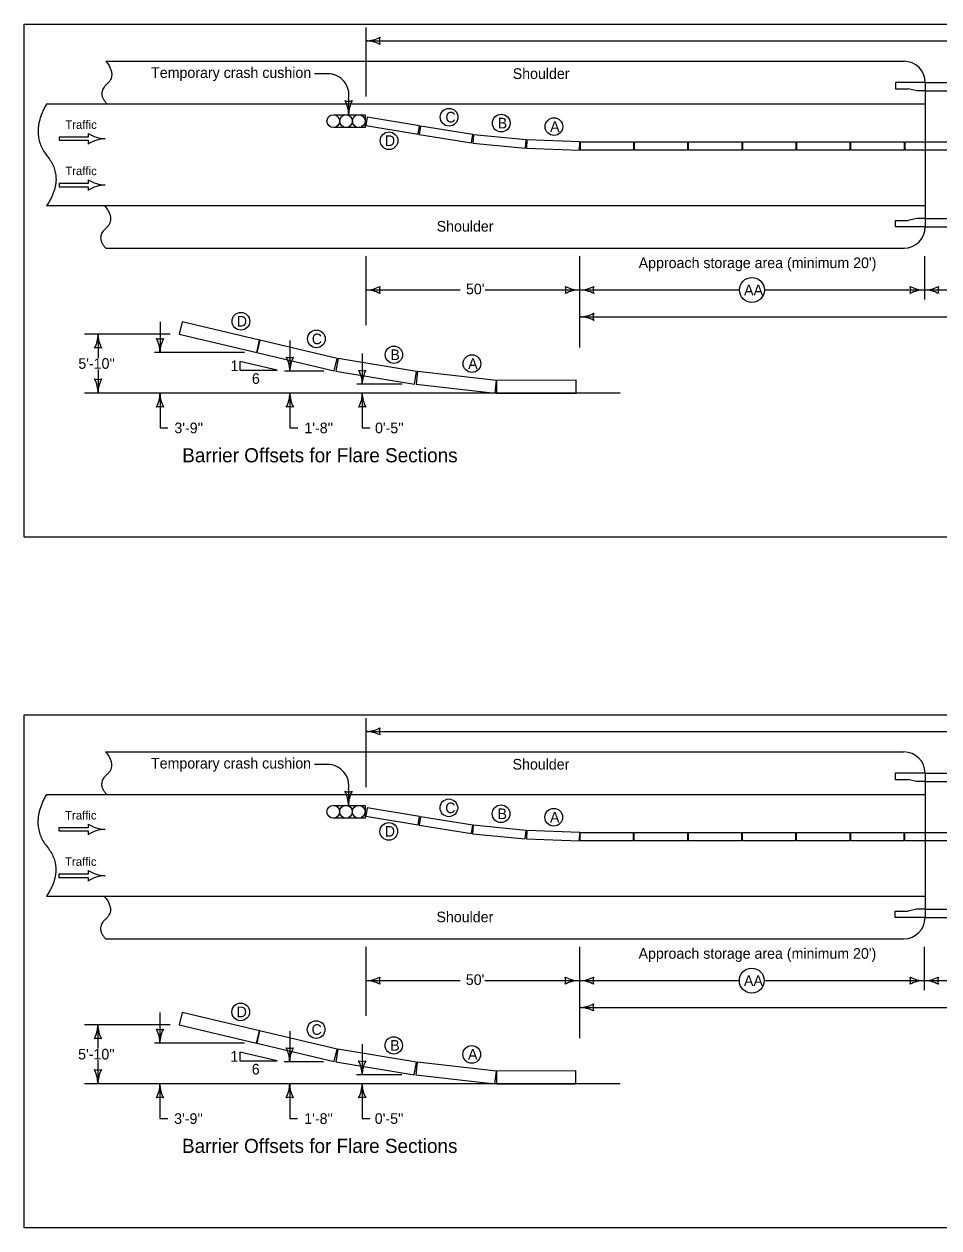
# Model space of a CAD drawing. Extents: x 10148 to 16528, y 8070 to 10905.
# Drawn here: x 10148 to 11441, y 9204 to 10905 of the extents above; entities that cross this region are included whole.
import ezdxf

# ---------------------------------------------------------------- set-up
doc = ezdxf.new("R2010")
doc.units = 0
for name, color, linetype in [('Sheet_Table Border', 7, 'Continuous'), ('SheetText', 7, 'Continuous'), ('TC_Barrier', 7, 'Continuous'), ('TC_Bridge', 7, 'Continuous'), ('TC_PCCPavement', 7, 'Continuous'), ('TC_ShoulderGranular', 7, 'Continuous')]:
    doc.layers.add(name, color=color, linetype=linetype)

msp = doc.modelspace()

# ---------------------------------------------------------------- linework, layer by layer
at = {"layer": 'Sheet_Table Border'}
for p, q in [((10148, 10904.5), (13253, 10904.5)), ((10148, 10179.5), (10148, 10904.5)), ((13253, 10179.5), (10148, 10179.5)), ((10147.7, 9928.8), (13252.7, 9928.8)), ((10147.7, 9203.8), (10147.7, 9928.8)), ((13252.7, 9203.8), (10147.7, 9203.8))]:
    msp.add_line(p, q, dxfattribs=at)
at = {"layer": 'SheetText'}
for p, q in [((10148, 10904.5), (10148, 10904.5)), ((10630.9, 10899.6), (10630.9, 10802.1)), ((10630.9, 10880.9), (11509.4, 10880.9)), ((10577.1, 10834.3), (10558.4, 10834.3)), ((10606.6, 10798.9), (10606.6, 10776.4)), ((10238.5, 10750), (10238.5, 10744.8)), ((10238.5, 10744.8), (10197.3, 10744.8)), ((10197.3, 10744.8), (10197.3, 10740.3)), ((10197.3, 10740.3), (10238.5, 10740.3)), ((10238.5, 10740.3), (10238.5, 10735)), ((10262.4, 10742.5), (10262.4, 10742.5)), ((10238.5, 10684.6), (10238.5, 10679.3)), ((10238.5, 10679.3), (10197.3, 10679.3)), ((10197.3, 10679.3), (10197.3, 10674.8)), ((10197.3, 10674.8), (10238.5, 10674.8)), ((10238.5, 10674.8), (10238.5, 10669.6)), ((10262.4, 10677.1), (10262.4, 10677.1)), ((10630.9, 10576.7), (10630.9, 10479.2)), ((10933.1, 10576.7), (10933.1, 10447.6)), ((11420.6, 10576.7), (11420.6, 10515.5)), ((10630.9, 10528.9), (10764.3, 10528.9)), ((10799.6, 10528.9), (10933.1, 10528.9)), ((10933.1, 10528.9), (11159.2, 10528.9)), ((11194.5, 10528.9), (11420.6, 10528.9)), ((11420.6, 10528.9), (11563.8, 10528.9)), ((10340, 10484), (10340, 10440.5)), ((10933.1, 10491), (11523.9, 10491)), ((10354.5, 10466.5), (10233.4, 10466.5)), ((10252.4, 10466.5), (10252.4, 10433)), ((10523.5, 10457.6), (10523.5, 10414.1)), ((10459.5, 10440.5), (10332.2, 10440.5)), ((10505.6, 10415.6), (10453, 10428)), ((10453, 10428), (10453, 10415.6)), ((10625.9, 10439), (10625.9, 10395.6)), ((10252.4, 10416.7), (10252.4, 10383.2)), ((10453, 10415.6), (10505.6, 10415.6)), ((10571.4, 10414.1), (10515.8, 10414.1)), ((10682.2, 10395.6), (10618.2, 10395.6)), ((10990.7, 10383.2), (10233.4, 10383.2)), ((10340, 10383.2), (10340, 10334)), ((10523.5, 10383.2), (10523.5, 10334)), ((10625.9, 10383.2), (10625.9, 10356.3)), ((10625.9, 10356.3), (10625.9, 10334)), ((10340, 10334), (10351.1, 10334)), ((10523.5, 10334), (10534.7, 10334)), ((10625.9, 10334), (10637.1, 10334)), ((10147.7, 9928.8), (10147.7, 9928.8)), ((10630.7, 9923.9), (10630.7, 9826.4)), ((10630.7, 9905.2), (11509.2, 9905.2)), ((10576.9, 9858.6), (10558.2, 9858.6)), ((10606.4, 9823.2), (10606.4, 9800.7)), ((10238.3, 9769.1), (10197, 9769.1)), ((10197, 9769.1), (10197, 9764.6)), ((10197, 9764.6), (10238.3, 9764.6)), ((10238.3, 9774.3), (10238.3, 9769.1)), ((10238.3, 9764.6), (10238.3, 9759.3)), ((10262.2, 9766.8), (10262.2, 9766.8)), ((10238.3, 9703.6), (10197, 9703.6)), ((10197, 9703.6), (10197, 9699.1)), ((10197, 9699.1), (10238.3, 9699.1)), ((10238.3, 9708.9), (10238.3, 9703.6)), ((10238.3, 9699.1), (10238.3, 9693.9)), ((10262.2, 9701.4), (10262.2, 9701.4)), ((10630.7, 9601), (10630.7, 9503.5)), ((10932.8, 9601), (10932.8, 9471.9)), ((11420.3, 9601), (11420.3, 9539.8)), ((10630.7, 9553.2), (10764.1, 9553.2)), ((10799.4, 9553.2), (10932.8, 9553.2)), ((10932.8, 9553.2), (11158.9, 9553.2)), ((11194.2, 9553.2), (11420.3, 9553.2)), ((11420.3, 9553.2), (11563.5, 9553.2)), ((10339.8, 9508.3), (10339.8, 9464.8)), ((10932.8, 9515.3), (11523.6, 9515.3)), ((10354.3, 9490.8), (10233.1, 9490.8)), ((10252.1, 9490.8), (10252.1, 9457.3)), ((10523.3, 9481.9), (10523.3, 9438.4)), ((10459.2, 9464.8), (10332, 9464.8)), ((10625.7, 9463.3), (10625.7, 9419.9)), ((10252.1, 9441), (10252.1, 9407.5)), ((10505.4, 9439.9), (10452.7, 9452.3)), ((10452.7, 9452.3), (10452.7, 9439.9)), ((10452.7, 9439.9), (10505.4, 9439.9)), ((10571.1, 9438.4), (10515.6, 9438.4)), ((10990.5, 9407.5), (10233.1, 9407.5)), ((10339.8, 9407.5), (10339.8, 9358.3)), ((10523.3, 9407.5), (10523.3, 9358.3)), ((10682, 9419.9), (10617.9, 9419.9)), ((10625.7, 9407.5), (10625.7, 9380.6)), ((10625.7, 9380.6), (10625.7, 9358.3)), ((10339.8, 9358.3), (10350.9, 9358.3)), ((10523.3, 9358.3), (10534.5, 9358.3)), ((10625.7, 9358.3), (10636.8, 9358.3))]:
    msp.add_line(p, q, dxfattribs=at)
for centre, radius in [((10748.6, 10773), 12.5), ((10822.3, 10764.6), 12.5), ((10896.9, 10759.7), 12.5), ((10663.7, 10739.8), 12.5), ((11176.8, 10528.9), 17.6), ((10454.3, 10484.7), 12.5), ((10561, 10459.8), 12.5), ((10670.6, 10437.4), 12.2), ((10781, 10424.8), 12.5), ((10748.3, 9797.3), 12.5), ((10822.1, 9788.9), 12.5), ((10896.6, 9784), 12.5), ((10663.4, 9764.1), 12.5), ((11176.6, 9553.2), 17.6), ((10454, 9509), 12.5), ((10560.7, 9484.1), 12.5), ((10670.4, 9461.7), 12.2), ((10780.7, 9449), 12.5)]:
    msp.add_circle(centre, radius, dxfattribs=at)
for centre, radius, start, end in [((10630.9, 10923.4), 42.5, 270, 298.0725), ((10666.5, 10880.9), 16.4, 162.2666, 197.7334), ((10630.9, 10838.4), 42.5, 61.9275, 90), ((10577.1, 10804.3), 30, 349.6463, 90), ((10606.6, 10812), 16.4, 252.2666, 287.7333), ((10564.1, 10776.4), 42.5, 360, 28.0725), ((10649.1, 10776.4), 42.5, 151.9275, 180), ((10264.4, 10790.9), 48.4, 237.618, 267.648), ((10264.4, 10694.2), 48.4, 92.352, 122.382), ((10264.4, 10725.4), 48.4, 237.618, 267.648), ((10264.4, 10628.8), 48.4, 92.352, 122.382), ((10630.9, 10571.4), 42.5, 270, 298.0725), ((10630.9, 10486.4), 42.5, 61.9275, 90), ((10666.5, 10528.9), 16.4, 162.2666, 197.7334), ((10897.4, 10528.9), 16.4, 342.2666, 17.7333), ((10933.1, 10571.4), 42.5, 241.9275, 270), ((10933.1, 10486.4), 42.5, 90, 118.0725), ((10933.1, 10571.4), 42.5, 270, 298.0725), ((10933.1, 10486.4), 42.5, 61.9275, 90), ((10968.7, 10528.9), 16.4, 162.2666, 197.7334), ((11384.9, 10528.9), 16.4, 342.2666, 17.7333), ((11420.6, 10571.4), 42.5, 241.9275, 270), ((11420.6, 10486.4), 42.5, 90, 118.0725), ((11420.6, 10571.4), 42.5, 270, 298.0725), ((11420.6, 10486.4), 42.5, 61.9275, 90), ((11456.2, 10528.9), 16.4, 162.2666, 197.7334), ((10933.1, 10533.5), 42.5, 270, 298.0725), ((10968.7, 10491), 16.4, 162.2666, 197.7334), ((10933.1, 10448.5), 42.5, 61.9275, 90), ((10209.9, 10466.5), 42.5, 331.9275, 0), ((10294.9, 10466.5), 42.5, 180, 208.0725), ((10340, 10476.2), 16.4, 252.2666, 287.7334), ((10297.5, 10440.5), 42.5, 0, 28.0725), ((10382.5, 10440.5), 42.5, 151.9275, 180), ((10252.4, 10430.9), 16.4, 72.2666, 107.7334), ((10523.5, 10449.8), 16.4, 252.2666, 287.7334), ((10481, 10414.1), 42.5, 0, 28.0725), ((10566, 10414.1), 42.5, 151.9275, 180), ((10625.9, 10431.2), 16.4, 252.2666, 287.7334), ((10583.4, 10395.6), 42.5, 0, 28.0725), ((10668.4, 10395.6), 42.5, 151.9275, 180), ((10252.4, 10418.9), 16.4, 252.2666, 287.7334), ((10209.9, 10383.2), 42.5, 0, 28.0725), ((10294.9, 10383.2), 42.5, 151.9275, 180), ((10297.5, 10383.2), 42.5, 331.9275, 0), ((10382.5, 10383.2), 42.5, 180, 208.0725), ((10481, 10383.2), 42.5, 331.9275, 0), ((10566, 10383.2), 42.5, 180, 208.0725), ((10583.4, 10383.2), 42.5, 331.9275, 0), ((10668.4, 10383.2), 42.5, 180, 208.0725), ((10340, 10347.6), 16.4, 72.2666, 107.7334), ((10523.5, 10347.6), 16.4, 72.2666, 107.7334), ((10625.9, 10347.6), 16.4, 72.2666, 107.7334), ((10630.7, 9947.7), 42.5, 270, 298.0725), ((10630.7, 9862.7), 42.5, 61.9275, 90), ((10666.3, 9905.2), 16.4, 162.2666, 197.7334), ((10576.9, 9828.6), 30, 349.6463, 90), ((10606.4, 9836.3), 16.4, 252.2666, 287.7333), ((10563.9, 9800.7), 42.5, 360, 28.0725), ((10648.9, 9800.7), 42.5, 151.9275, 180), ((10264.2, 9815.2), 48.4, 237.618, 267.648), ((10264.2, 9718.5), 48.4, 92.352, 122.382), ((10264.2, 9749.7), 48.4, 237.618, 267.648), ((10264.2, 9653.1), 48.4, 92.352, 122.382), ((10630.7, 9595.7), 42.5, 270, 298.0725), ((10666.3, 9553.2), 16.4, 162.2666, 197.7334), ((10897.2, 9553.2), 16.4, 342.2666, 17.7333), ((10932.8, 9595.7), 42.5, 241.9275, 270), ((10932.8, 9595.7), 42.5, 270, 298.0725), ((10968.5, 9553.2), 16.4, 162.2666, 197.7334), ((11384.7, 9553.2), 16.4, 342.2666, 17.7333), ((11420.3, 9595.7), 42.5, 241.9275, 270), ((11420.3, 9595.7), 42.5, 270, 298.0725), ((11456, 9553.2), 16.4, 162.2666, 197.7334), ((10630.7, 9510.7), 42.5, 61.9275, 90), ((10932.8, 9510.7), 42.5, 90, 118.0725), ((10932.8, 9510.7), 42.5, 61.9275, 90), ((11420.3, 9510.7), 42.5, 90, 118.0725), ((11420.3, 9510.7), 42.5, 61.9275, 90), ((10932.8, 9557.8), 42.5, 270, 298.0725), ((10932.8, 9472.8), 42.5, 61.9275, 90), ((10968.5, 9515.3), 16.4, 162.2666, 197.7334), ((10209.6, 9490.8), 42.5, 331.9275, 0), ((10294.6, 9490.8), 42.5, 180, 208.0725), ((10339.8, 9500.5), 16.4, 252.2666, 287.7334), ((10297.3, 9464.8), 42.5, 0, 28.0725), ((10382.3, 9464.8), 42.5, 151.9275, 180), ((10252.1, 9455.2), 16.4, 72.2666, 107.7334), ((10523.3, 9474.1), 16.4, 252.2666, 287.7334), ((10480.8, 9438.4), 42.5, 0, 28.0725), ((10565.8, 9438.4), 42.5, 151.9275, 180), ((10625.7, 9455.5), 16.4, 252.2666, 287.7334), ((10583.2, 9419.9), 42.5, 0, 28.0725), ((10668.2, 9419.9), 42.5, 151.9275, 180), ((10252.1, 9443.2), 16.4, 252.2666, 287.7334), ((10209.6, 9407.5), 42.5, 0, 28.0725), ((10294.6, 9407.5), 42.5, 151.9275, 180), ((10297.3, 9407.5), 42.5, 331.9275, 0), ((10382.3, 9407.5), 42.5, 180, 208.0725), ((10480.8, 9407.5), 42.5, 331.9275, 0), ((10565.8, 9407.5), 42.5, 180, 208.0725), ((10583.2, 9407.5), 42.5, 331.9275, 0), ((10668.2, 9407.5), 42.5, 180, 208.0725), ((10339.8, 9371.9), 16.4, 72.2666, 107.7334), ((10523.3, 9371.9), 16.4, 72.2666, 107.7334), ((10625.7, 9371.9), 16.4, 72.2666, 107.7334)]:
    msp.add_arc(centre, radius, start, end, dxfattribs=at)
at = {"layer": 'TC_Barrier'}
for p, q in [((10585, 10776.4), (10630, 10776.4)), ((10630, 10776.4), (10630, 10758.4)), ((10630, 10758.4), (10585, 10758.4)), ((10628.8, 10764.1), (10630.1, 10763.8)), ((10630.6, 10760.4), (10630.6, 10760.4)), ((10584.8, 9800.7), (10629.8, 9800.7)), ((10629.8, 9800.7), (10629.8, 9782.7)), ((10629.8, 9782.7), (10584.8, 9782.7)), ((10628.6, 9788.4), (10629.9, 9788.1)), ((10630.3, 9784.7), (10630.3, 9784.7))]:
    msp.add_line(p, q, dxfattribs=at)
for points in [[(10706.9, 10760.8), (10632.8, 10772.9), (10630.9, 10761.1), (10704.9, 10748.9)], [(10782.3, 10748.4), (10708.3, 10760.5), (10706.4, 10748.7), (10780.4, 10736.6)], [(10857.8, 10741.2), (10783.1, 10748.3), (10782, 10736.3), (10856.6, 10729.2)], [(10933.5, 10738.2), (10858.6, 10741.2), (10858.1, 10729.2), (10933.1, 10726.2)], [(10934.3, 10738.2), (11009.3, 10738.2), (11009.3, 10726.2), (10934.3, 10726.2)], [(11010.8, 10738.2), (11085.8, 10738.2), (11085.8, 10726.2), (11010.8, 10726.2)], [(11087.3, 10738.2), (11162.3, 10738.2), (11162.3, 10726.2), (11087.3, 10726.2)], [(11163.8, 10738.2), (11238.8, 10738.2), (11238.8, 10726.2), (11163.8, 10726.2)], [(11240.3, 10738.2), (11315.3, 10738.2), (11315.3, 10726.2), (11240.3, 10726.2)], [(11316.8, 10738.2), (11391.8, 10738.2), (11391.8, 10726.2), (11316.8, 10726.2)], [(11393.3, 10738.2), (11468.3, 10738.2), (11468.3, 10726.2), (11393.3, 10726.2)], [(10480.8, 10458.1), (10371.3, 10484), (10367.2, 10466.5), (10476.6, 10440.6)], [(10590.6, 10432.2), (10481.1, 10458.1), (10476.9, 10440.5), (10586.4, 10414.6)], [(10702.6, 10413.5), (10591.7, 10431.9), (10588.7, 10414.1), (10699.7, 10395.7)], [(10815.7, 10401.1), (10703.9, 10413.5), (10701.9, 10395.6), (10813.8, 10383.2)], [(10928.2, 10401.3), (10815.7, 10401.2), (10815.7, 10383.2), (10928.2, 10383.3)], [(10706.6, 9785.1), (10632.6, 9797.2), (10630.7, 9785.4), (10704.7, 9773.2)], [(10782.1, 9772.7), (10708.1, 9784.8), (10706.2, 9773), (10780.2, 9760.9)], [(10857.5, 9765.5), (10782.9, 9772.6), (10781.7, 9760.6), (10856.4, 9753.5)], [(10933.3, 9762.5), (10858.4, 9765.5), (10857.9, 9753.5), (10932.8, 9750.5)], [(10934, 9762.5), (11009, 9762.5), (11009, 9750.5), (10934, 9750.5)], [(11010.5, 9762.5), (11085.5, 9762.5), (11085.5, 9750.5), (11010.5, 9750.5)], [(11087, 9762.5), (11162, 9762.5), (11162, 9750.5), (11087, 9750.5)], [(11163.5, 9762.5), (11238.5, 9762.5), (11238.5, 9750.5), (11163.5, 9750.5)], [(11240, 9762.5), (11315, 9762.5), (11315, 9750.5), (11240, 9750.5)], [(11316.5, 9762.5), (11391.5, 9762.5), (11391.5, 9750.5), (11316.5, 9750.5)], [(11393, 9762.5), (11468, 9762.5), (11468, 9750.5), (11393, 9750.5)], [(10480.6, 9482.4), (10371.1, 9508.3), (10366.9, 9490.8), (10476.4, 9464.9)], [(10590.3, 9456.5), (10480.8, 9482.4), (10476.7, 9464.8), (10586.2, 9438.9)], [(10702.4, 9437.8), (10591.4, 9456.2), (10588.5, 9438.4), (10699.5, 9420)], [(10815.5, 9425.4), (10703.7, 9437.8), (10701.7, 9419.9), (10813.5, 9407.5)], [(10928, 9425.6), (10815.5, 9425.5), (10815.5, 9407.5), (10928, 9407.6)]]:
    msp.add_lwpolyline(points, close=True, dxfattribs=at)
for centre in [(10585, 10767.4), (10585, 10767.4), (10603, 10767.4), (10603, 10767.4), (10621, 10767.4), (10621, 10767.4), (10584.8, 9791.7), (10584.8, 9791.7), (10602.8, 9791.7), (10602.8, 9791.7), (10620.8, 9791.7), (10620.8, 9791.7)]:
    msp.add_circle(centre, 9, dxfattribs=at)
at = {"layer": 'TC_Bridge'}
for p, q in [((11421.8, 10822), (11379.8, 10822)), ((11379.8, 10822), (11379.8, 10813)), ((11421.8, 10822), (11421.8, 10618)), ((11421.8, 10822), (11567.8, 10822)), ((11379.8, 10813), (11397.8, 10813)), ((11409.8, 10810), (11397.8, 10813)), ((11421.8, 10810), (11409.8, 10810)), ((11421.8, 10810), (11567.8, 10810)), ((11409.8, 10630), (11397.8, 10627)), ((11421.8, 10630), (11409.8, 10630)), ((11421.8, 10630), (11567.8, 10630)), ((11379.8, 10627), (11397.8, 10627)), ((11379.8, 10618), (11379.8, 10627)), ((11421.8, 10618), (11379.8, 10618)), ((11421.8, 10618), (11567.8, 10618)), ((11421.5, 9846.3), (11379.5, 9846.3)), ((11379.5, 9846.3), (11379.5, 9837.3)), ((11379.5, 9837.3), (11397.5, 9837.3)), ((11409.5, 9834.3), (11397.5, 9837.3)), ((11421.5, 9834.3), (11409.5, 9834.3)), ((11421.5, 9846.3), (11421.5, 9642.3)), ((11421.5, 9846.3), (11567.5, 9846.3)), ((11421.5, 9834.3), (11567.5, 9834.3)), ((11379.5, 9651.3), (11397.5, 9651.3)), ((11379.5, 9642.3), (11379.5, 9651.3)), ((11409.5, 9654.3), (11397.5, 9651.3)), ((11421.5, 9654.3), (11409.5, 9654.3)), ((11421.5, 9654.3), (11567.5, 9654.3)), ((11421.5, 9642.3), (11379.5, 9642.3)), ((11421.5, 9642.3), (11567.5, 9642.3))]:
    msp.add_line(p, q, dxfattribs=at)
at = {"layer": 'TC_PCCPavement'}
for p, q in [((10179.7, 10792), (11421.8, 10792)), ((10179.7, 10648), (11421.8, 10648)), ((10179.4, 9816.3), (11421.5, 9816.3)), ((10179.4, 9672.3), (11421.5, 9672.3))]:
    msp.add_line(p, q, dxfattribs=at)
for points in [[(10179.7, 10792), (10155, 10749.3), (10205.8, 10687.1), (10179.7, 10648)], [(10179.4, 9816.3), (10154.8, 9773.6), (10205.6, 9711.4), (10179.4, 9672.3)]]:
    msp.add_open_spline(points, degree=2, dxfattribs=at)
at = {"layer": 'TC_ShoulderGranular'}
for p, q in [((10263.3, 10852), (11391.8, 10852)), ((10263.3, 10588), (11391.8, 10588)), ((10263, 9876.3), (11391.5, 9876.3)), ((10263, 9612.3), (11391.5, 9612.3))]:
    msp.add_line(p, q, dxfattribs=at)
for centre, start, end in [((11391.8, 10822), 0, 90), ((11391.8, 10618), 270, 360), ((11391.5, 9846.3), 0, 90), ((11391.5, 9642.3), 270, 360)]:
    msp.add_arc(centre, 30, start, end, dxfattribs=at)
for points in [[(10263.3, 10852), (10279.3, 10832.6), (10250.4, 10807), (10264.9, 10792)], [(10261.7, 10647.9), (10277.7, 10628.6), (10248.8, 10603), (10263.3, 10588)], [(10263, 9876.3), (10279.1, 9856.9), (10250.2, 9831.3), (10264.6, 9816.3)], [(10261.4, 9672.2), (10277.5, 9652.9), (10248.6, 9627.3), (10263, 9612.3)]]:
    msp.add_open_spline(points, degree=2, dxfattribs=at)

# ---------------------------------------------------------------- texts
at = {"layer": 'SheetText'}
for s, height, p in [('Temporary crash cushion', 15, (10327.4, 10828.5)), ('Shoulder', 15, (10838.6, 10827.1)), ('Traffic', 12, (10206, 10756.5)), ('C', 15, (10743.4, 10765.5)), ('B', 15, (10817.4, 10757.1)), ('A', 15, (10891.5, 10752.2)), ('D', 15, (10657.9, 10732.3)), ('Traffic', 12, (10206, 10691.1)), ('Shoulder', 15, (10731.1, 10611.4)), ("Approach storage area (minimum 20')", 15, (11016.7, 10559.8)), ("50'", 15, (10772.5, 10522.8)), ('AA', 15, (11165.7, 10521.4)), ('D', 15, (10448.5, 10477.2)), ('C', 15, (10554.5, 10452.3)), ('B', 15, (10665.7, 10429.9)), ("5'-10''", 15, (10224.5, 10417.5)), ('1', 15, (10439.7, 10414.4)), ('A', 15, (10775.6, 10417.3)), ('6', 15, (10469.9, 10396.3)), ("3'-9''", 15, (10360.3, 10326.5)), ("1'-8''", 15, (10544.1, 10326.5)), ("0'-5''", 15, (10643.9, 10326.5)), ('Barrier Offsets for Flare Sections', 20, (10371.3, 10285.4)), ('Temporary crash cushion', 15, (10327.2, 9852.8)), ('Shoulder', 15, (10838.4, 9851.4)), ('C', 15, (10743.2, 9789.8)), ('B', 15, (10817.1, 9781.4)), ('Traffic', 12, (10205.7, 9780.8)), ('A', 15, (10891.3, 9776.5)), ('D', 15, (10657.7, 9756.6)), ('Traffic', 12, (10205.7, 9715.4)), ('Shoulder', 15, (10730.8, 9635.7)), ("Approach storage area (minimum 20')", 15, (11016.5, 9584.1)), ("50'", 15, (10772.3, 9547.1)), ('AA', 15, (11165.5, 9545.7)), ('D', 15, (10448.3, 9501.5)), ('C', 15, (10554.2, 9476.6)), ("5'-10''", 15, (10224.2, 9441.8)), ('B', 15, (10665.4, 9454.2)), ('A', 15, (10775.4, 9441.6)), ('1', 15, (10439.4, 9438.7)), ('6', 15, (10469.7, 9420.6)), ("3'-9''", 15, (10360, 9350.8)), ("1'-8''", 15, (10543.9, 9350.8)), ("0'-5''", 15, (10643.6, 9350.8)), ('Barrier Offsets for Flare Sections', 20, (10371.1, 9309.7))]:
    msp.add_text(s, height=height, dxfattribs=at).set_placement(p)

doc.saveas('drawing.dxf')
